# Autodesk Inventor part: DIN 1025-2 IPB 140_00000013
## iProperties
Created: 2006-02
Part Number: DIN 1025-2 IPB 140_00000013
Material: Default
Document SubType Name: Modeling
Designer: 40664
Manufacturer: Standard
Standards Organization: Custom
Stock Number: DIN 1025-2 IPB 140
Mass: 11082.7 g
Surface Area: 20865.2 cm^2
Volume: 11082.7 cm^3
Density: 1 g/cm^3
G_L: 2580.000 mm
G_W: 140.000 mm
G_H: 140.000 mm
AFG_Item: IPB 140
CSToolsMass: 11.0
CSToolsVolume: 11082691.0
CSToolsArea: 20865.0
Author: 40664
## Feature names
1. AFG_Detailed_DIN 1025-2 IPB 140_00000013 [Extrusion]
2. AFG_Simplified_DIN 1025-2 IPB 140_00000013 [Extrusion]
